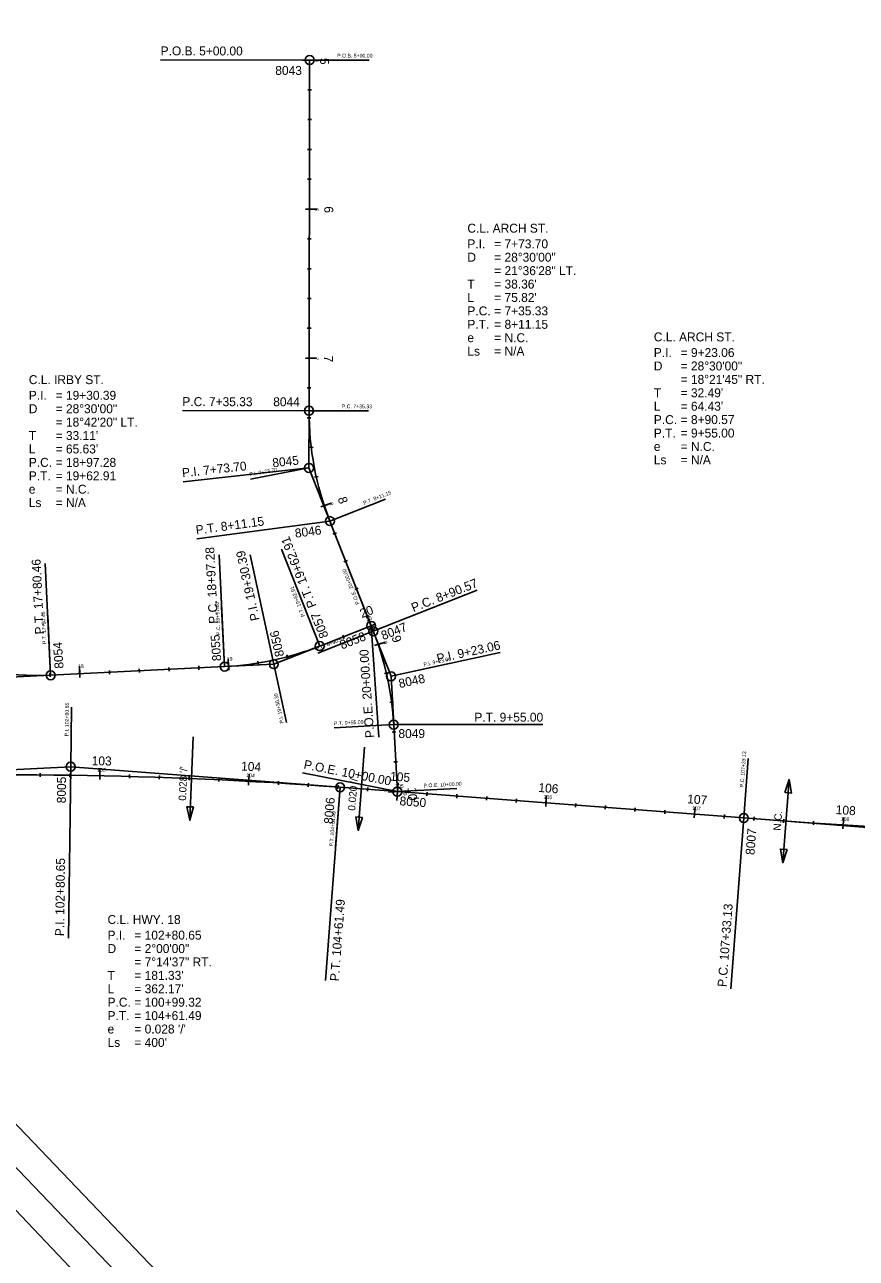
# Model space of a CAD drawing. Extents: x 1708585 to 1714116, y 541444 to 545437.
# Drawn here: x 1712258 to 1712816, y 543987 to 544815 of the extents above; entities that cross this region are included whole.
import ezdxf

# ---------------------------------------------------------------- set-up
doc = ezdxf.new("R2010")
doc.units = 0
for name, color, linetype in [('CL_Highway_1', 7, 'Continuous'), ('CL_Highway_1_40_PText', 7, 'Continuous'), ('CL_Highway_1_40_Sta', 7, 'Continuous'), ('CL_Highway_1_PText', 7, 'Continuous'), ('CL_Highway_1_Sta', 7, 'Continuous'), ('CL_Highway_1_Sta_Minor_Text', 7, 'Continuous'), ('CL_Highway_1_Tangent', 7, 'Continuous'), ('CL_Railroad', 7, 'Continuous'), ('CL_XS_2', 7, 'Continuous'), ('CL_XS_2_40_PText', 7, 'Continuous'), ('CL_XS_2_40_Sta', 7, 'Continuous'), ('CL_XS_2_PText', 7, 'Continuous'), ('CL_XS_2_Sta', 7, 'Continuous'), ('CL_XS_2_Tangent', 7, 'Continuous'), ('CL_XS_3', 7, 'Continuous'), ('CL_XS_3_40_PText', 7, 'Continuous'), ('CL_XS_3_40_Sta', 7, 'Continuous'), ('CL_XS_3_PText', 7, 'Continuous'), ('CL_XS_3_Sta', 7, 'Continuous'), ('CL_XS_3_Sta_Minor_Text', 7, 'Continuous'), ('CL_XS_3_Tangent', 7, 'Continuous'), ('CurveData_100', 7, 'Continuous'), ('Point_CL_Highway_1', 7, 'Continuous'), ('Point_CL_XS_2', 7, 'Continuous'), ('Point_CL_XS_3', 7, 'Continuous'), ('Point_Number', 7, 'Continuous'), ('R_SE_Slope', 7, 'Continuous')]:
    doc.layers.add(name, color=color, linetype=linetype)

msp = doc.modelspace()

# ---------------------------------------------------------------- linework, layer by layer
at = {"layer": 'CL_Highway_1'}
msp.add_line((1712469.8, 544303.56), (1712740.66, 544282.94), dxfattribs=at)
for centre, radius, start, end in [((1712252.32, 541447.04), 2864.79, 85.64618, 92.88967), ((1713175.62, 549995.98), 5729.58, 265.64618, 270.33927)]:
    msp.add_arc(centre, radius, start, end, dxfattribs=at)
at = {"layer": 'CL_Highway_1_40_PText'}
for points in [[(1712288.99, 544317.32), (1712289.51, 544357.32)], [(1712740.66, 544282.94), (1712743.69, 544322.82)], [(1712469.8, 544303.56), (1712466.76, 544263.67)]]:
    msp.add_lwpolyline(points, dxfattribs=at)
at = {"layer": 'CL_Highway_1_40_Sta'}
for points in [[(1712268.52, 544313.03), (1712268.51, 544310.53)], [(1712288.53, 544312.85), (1712288.5, 544310.35)], [(1712308.56, 544313.77), (1712308.46, 544308.77)], [(1712328.54, 544312.06), (1712328.47, 544309.56)], [(1712348.54, 544311.46), (1712348.46, 544308.96)], [(1712368.54, 544310.72), (1712368.43, 544308.22)], [(1712388.52, 544309.84), (1712388.41, 544307.34)], [(1712408.58, 544310.06), (1712408.3, 544305.07)], [(1712428.48, 544307.66), (1712428.33, 544305.16)], [(1712448.45, 544306.36), (1712448.28, 544303.86)], [(1712468.41, 544304.92), (1712468.22, 544302.42)], [(1712488.35, 544303.4), (1712488.16, 544300.91)], [(1712508.39, 544303.13), (1712508.01, 544298.14)], [(1712528.23, 544300.36), (1712528.04, 544297.87)], [(1712548.18, 544298.84), (1712547.99, 544296.35)], [(1712568.12, 544297.33), (1712567.93, 544294.83)], [(1712588.06, 544295.81), (1712587.87, 544293.31)], [(1712608.1, 544295.54), (1712607.72, 544290.55)], [(1712627.94, 544292.77), (1712627.76, 544290.28)], [(1712647.89, 544291.25), (1712647.7, 544288.76)], [(1712667.83, 544289.73), (1712667.64, 544287.24)], [(1712687.77, 544288.22), (1712687.58, 544285.72)], [(1712707.81, 544287.94), (1712707.43, 544282.96)], [(1712727.66, 544285.18), (1712727.47, 544282.69)], [(1712747.6, 544283.66), (1712747.41, 544281.17)], [(1712767.54, 544282.21), (1712767.36, 544279.71)], [(1712787.49, 544280.82), (1712787.32, 544278.32)], [(1712807.52, 544280.74), (1712807.2, 544275.75)]]:
    msp.add_lwpolyline(points, dxfattribs=at)
at = {"layer": 'CL_Highway_1_PText'}
for points in [[(1712288.99, 544317.32), (1712287.53, 544202.33)], [(1712469.8, 544303.56), (1712459.93, 544173.93)], [(1712740.66, 544282.94), (1712731.93, 544168.27)]]:
    msp.add_lwpolyline(points, dxfattribs=at)
at = {"layer": 'CL_Highway_1_Sta'}
for points in [[(1712308.61, 544316.27), (1712308.51, 544311.27)], [(1712408.71, 544312.56), (1712408.44, 544307.57)], [(1712508.65, 544306.62), (1712507.74, 544294.65)], [(1712608.29, 544298.03), (1712607.91, 544293.04)], [(1712708, 544290.44), (1712707.62, 544285.45)], [(1712807.68, 544283.24), (1712807.36, 544278.25)]]:
    msp.add_lwpolyline(points, dxfattribs=at)
at = {"layer": 'CL_Highway_1_Tangent'}
for p, q in [((1712107.9, 544308.18), (1712288.99, 544317.32)), ((1712288.99, 544317.32), (1712469.8, 544303.56)), ((1712740.66, 544282.94), (1712974.76, 544265.11))]:
    msp.add_line(p, q, dxfattribs=at)
at = {"layer": 'CL_Railroad'}
for p, q in [((1710952.7, 545436.87), (1713371.13, 542906.81)), ((1710938.24, 545423.05), (1713356.67, 542892.99)), ((1710923.78, 545409.23), (1713342.21, 542879.17))]:
    msp.add_line(p, q, dxfattribs=at)
at = {"layer": 'CL_XS_2'}
for p, q in [((1712456.08, 544398.29), (1712490.59, 544411.89)), ((1712275.53, 544378.82), (1712392.21, 544384.53))]:
    msp.add_line(p, q, dxfattribs=at)
for centre, start, end in [((1712265.7, 544579.61), 224.05036, 272.80306), ((1712382.38, 544585.33), 272.80306, 291.50855)]:
    msp.add_arc(centre, 201.04, start, end, dxfattribs=at)
at = {"layer": 'CL_XS_2_40_PText'}
for points in [[(1712490.59, 544411.89), (1712475.93, 544449.1)], [(1712456.08, 544398.29), (1712441.42, 544435.5)], [(1712392.21, 544384.53), (1712390.25, 544424.48)], [(1712275.53, 544378.82), (1712273.57, 544418.77)], [(1712425.28, 544386.15), (1712433.7, 544347.05)]]:
    msp.add_lwpolyline(points, dxfattribs=at)
at = {"layer": 'CL_XS_2_40_Sta'}
for points in [[(1712489.68, 544414.21), (1712491.51, 544409.56)], [(1712471.53, 544405.72), (1712472.44, 544403.39)], [(1712452.93, 544398.41), (1712453.81, 544396.07)], [(1712434.02, 544392.33), (1712434.66, 544389.91)], [(1712294.93, 544382.27), (1712295.17, 544377.28)], [(1712314.96, 544382), (1712315.08, 544379.5)], [(1712334.94, 544382.98), (1712335.06, 544380.48)], [(1712354.91, 544383.96), (1712355.04, 544381.46)], [(1712374.89, 544384.93), (1712375.01, 544382.44)], [(1712394.77, 544387.18), (1712395.08, 544382.19)], [(1712414.59, 544388.15), (1712414.99, 544385.69)], [(1712275.01, 544380.04), (1712275.13, 544377.55)]]:
    msp.add_lwpolyline(points, dxfattribs=at)
at = {"layer": 'CL_XS_2_PText'}
for points in [[(1712456.08, 544398.29), (1712430.42, 544463.42)], [(1712388.54, 544459.44), (1712392.21, 544384.53)], [(1712409.49, 544459.47), (1712425.28, 544386.15)], [(1712271.86, 544453.73), (1712275.53, 544378.82)], [(1712490.59, 544411.89), (1712495.76, 544337.07)]]:
    msp.add_lwpolyline(points, dxfattribs=at)
at = {"layer": 'CL_XS_2_Sta'}
for p, q in [((1712492.43, 544407.24), (1712488.76, 544416.54)), ((1712394.93, 544384.68), (1712394.61, 544389.67)), ((1712295.05, 544379.77), (1712294.8, 544384.77))]:
    msp.add_line(p, q, dxfattribs=at)
at = {"layer": 'CL_XS_2_Tangent'}
for points in [[(1712121.21, 544439.84), (1712184.54, 544374.36), (1712275.53, 544378.82)], [(1712392.21, 544384.53), (1712425.28, 544386.15), (1712456.08, 544398.29)]]:
    msp.add_lwpolyline(points, dxfattribs=at)
at = {"layer": 'CL_XS_3'}
for p, q in [((1712449.32, 544791.52), (1712448.91, 544556.19)), ((1712462.91, 544482.13), (1712492.03, 544408.24)), ((1712505.73, 544345.57), (1712508.2, 544300.63))]:
    msp.add_line(p, q, dxfattribs=at)
for centre, start, end in [((1712649.95, 544555.84), 179.90067, 201.50855), ((1712304.99, 544334.53), 3.14618, 21.50855)]:
    msp.add_arc(centre, 201.04, start, end, dxfattribs=at)
at = {"layer": 'CL_XS_3_40_PText'}
for points in [[(1712449.32, 544791.52), (1712489.32, 544791.45)], [(1712448.91, 544556.19), (1712488.91, 544556.12)], [(1712448.85, 544517.82), (1712409.54, 544510.39)], [(1712462.91, 544482.13), (1712500.13, 544496.8)], [(1712492.03, 544408.24), (1712454.82, 544393.58)], [(1712503.94, 544378.01), (1712543.02, 544386.55)], [(1712505.73, 544345.57), (1712465.79, 544343.37)], [(1712508.2, 544300.63), (1712548.14, 544302.83)]]:
    msp.add_lwpolyline(points, dxfattribs=at)
at = {"layer": 'CL_XS_3_40_Sta'}
for points in [[(1712451.82, 544791.52), (1712446.82, 544791.52)], [(1712450.54, 544771.52), (1712448.04, 544771.52)], [(1712450.5, 544751.52), (1712448, 544751.52)], [(1712450.47, 544731.52), (1712447.97, 544731.52)], [(1712450.43, 544711.52), (1712447.93, 544711.52)], [(1712451.65, 544691.52), (1712446.65, 544691.53)], [(1712450.36, 544671.52), (1712447.86, 544671.52)], [(1712450.33, 544651.52), (1712447.83, 544651.52)], [(1712450.29, 544631.52), (1712447.79, 544631.52)], [(1712450.26, 544611.52), (1712447.76, 544611.52)], [(1712451.47, 544591.52), (1712446.47, 544591.53)], [(1712450.19, 544571.52), (1712447.69, 544571.52)], [(1712450.21, 544551.55), (1712447.71, 544551.49)], [(1712451.62, 544531.73), (1712449.14, 544531.43)], [(1712455, 544512.15), (1712452.56, 544511.61)], [(1712461.49, 544493.4), (1712456.74, 544491.83)], [(1712467.32, 544474.36), (1712464.99, 544473.44)], [(1712474.65, 544455.75), (1712472.33, 544454.83)], [(1712481.98, 544437.14), (1712479.66, 544436.22)], [(1712489.32, 544418.53), (1712486.99, 544417.62)], [(1712497.65, 544400.2), (1712492.91, 544398.58)], [(1712502, 544380.45), (1712499.56, 544379.89)], [(1712505.58, 544360.66), (1712503.11, 544360.34)], [(1712507.25, 544340.64), (1712504.75, 544340.51)], [(1712508.35, 544320.67), (1712505.85, 544320.54)], [(1712510.69, 544300.77), (1712505.7, 544300.5)]]:
    msp.add_lwpolyline(points, dxfattribs=at)
at = {"layer": 'CL_XS_3_PText'}
for points in [[(1712449.32, 544791.52), (1712349.32, 544791.69)], [(1712448.91, 544556.19), (1712363.91, 544556.33)], [(1712448.85, 544517.82), (1712364.35, 544508.59)], [(1712462.91, 544482.13), (1712373.71, 544470.18)], [(1712492.03, 544408.24), (1712561.81, 544435.74)], [(1712503.94, 544378.01), (1712577.21, 544394.02)], [(1712505.73, 544345.57), (1712605.73, 544345.56)], [(1712508.2, 544300.63), (1712444.42, 544313.18)]]:
    msp.add_lwpolyline(points, dxfattribs=at)
at = {"layer": 'CL_XS_3_Sta'}
for p, q in [((1712454.32, 544791.51), (1712444.32, 544791.53)), ((1712454.15, 544691.51), (1712449.15, 544691.52)), ((1712453.97, 544591.51), (1712448.97, 544591.52)), ((1712463.86, 544494.19), (1712459.11, 544492.61)), ((1712500.01, 544401), (1712495.28, 544399.39)), ((1712514.19, 544300.96), (1712502.21, 544300.3))]:
    msp.add_line(p, q, dxfattribs=at)
at = {"layer": 'CL_XS_3_Tangent'}
for points in [[(1712448.91, 544556.19), (1712448.85, 544517.82), (1712462.91, 544482.13)], [(1712492.03, 544408.24), (1712503.94, 544378.01), (1712505.73, 544345.57)]]:
    msp.add_lwpolyline(points, dxfattribs=at)
at = {"layer": 'Point_CL_Highway_1'}
for centre in [(1712288.99, 544317.32), (1712469.8, 544303.56), (1712740.66, 544282.94)]:
    msp.add_circle(centre, 3, dxfattribs=at)
at = {"layer": 'Point_CL_XS_2'}
for centre in [(1712490.59, 544411.89), (1712456.08, 544398.29), (1712425.28, 544386.15), (1712275.53, 544378.74), (1712392.21, 544384.53)]:
    msp.add_circle(centre, 3, dxfattribs=at)
at = {"layer": 'Point_CL_XS_3'}
msp.add_lwpolyline([(1712490.59, 544411.89), (1712489.49, 544414.68), (1712490.59, 544411.89), (1712487.8, 544410.79), (1712490.59, 544411.89), (1712491.69, 544409.1), (1712490.59, 544411.89), (1712493.38, 544412.99)], dxfattribs=at)
for centre in [(1712449.32, 544791.52), (1712448.91, 544556.19), (1712448.85, 544517.82), (1712462.91, 544482.13), (1712492.03, 544408.24), (1712503.94, 544378.01), (1712505.73, 544345.57), (1712508.2, 544300.63)]:
    msp.add_circle(centre, 3, dxfattribs=at)
at = {"layer": 'R_SE_Slope'}
for p, q in [((1712368.83, 544281.43), (1712371.13, 544337.38)), ((1712481.92, 544274.55), (1712486.17, 544330.39)), ((1712766.81, 544252.93), (1712771.07, 544308.77))]:
    msp.add_line(p, q, dxfattribs=at)
for points in [[(1712768.14, 544299.97), (1712772.63, 544299.63), (1712771.07, 544308.77)], [(1712371.44, 544290.33), (1712366.95, 544290.52), (1712368.83, 544281.43)], [(1712484.85, 544283.36), (1712480.36, 544283.7), (1712481.92, 544274.55)], [(1712769.74, 544261.74), (1712765.25, 544262.08), (1712766.81, 544252.93)]]:
    msp.add_lwpolyline(points, close=True, dxfattribs=at)

# ---------------------------------------------------------------- texts
at = {"layer": 'CL_Highway_1_40_PText'}
for s, rotation, p in [('P.I. 102+80.65', 89.26792, (1712287.51, 544337.75)), ('P.C. 107+33.13', 85.64618, (1712740.47, 544303.58)), ('P.T. 104+61.49', 85.64618, (1712465.02, 544263.81))]:
    msp.add_text(s, height=2.5, rotation=rotation, dxfattribs=at).set_placement(p)
at = {"layer": 'CL_Highway_1_40_Sta'}
for s, rotation, p in [('103', 358.87604, (1712306.69, 544314.06)), ('104', 356.87604, (1712406.72, 544310.42)), ('105', 355.64618, (1712506.54, 544303.52)), ('106', 355.64618, (1712606.19, 544295.93)), ('107', 355.64618, (1712705.96, 544288.34)), ('108', 356.31486, (1712805.67, 544281.11))]:
    msp.add_text(s, height=2.5, rotation=rotation, dxfattribs=at).set_placement(p)
at = {"layer": 'CL_Highway_1_PText'}
for s, rotation, p in [('P.I. 102+80.65', 89.26792, (1712284.54, 544203.62)), ('P.T. 104+61.49', 85.64618, (1712468.91, 544173.25)), ('P.C. 107+33.13', 85.64618, (1712729, 544169.39))]:
    msp.add_text(s, height=6, rotation=rotation, dxfattribs=at).set_placement(p)
at = {"layer": 'CL_Highway_1_Sta'}
msp.add_text('105', height=6, rotation=355.64618, dxfattribs=at).set_placement((1712503.12, 544308.04))
at = {"layer": 'CL_Highway_1_Sta_Minor_Text'}
for s, rotation, p in [('103', 358.87604, (1712303.03, 544318.38)), ('104', 356.87604, (1712403.21, 544314.86)), ('106', 355.64618, (1712602.67, 544300.46)), ('107', 355.64618, (1712702.54, 544292.86)), ('108', 356.31486, (1712802.2, 544285.6))]:
    msp.add_text(s, height=6, rotation=rotation, dxfattribs=at).set_placement(p)
at = {"layer": 'CL_XS_2_40_PText'}
for s, rotation, p in [('P.O.E. 20+00.00', 111.50855, (1712482.87, 544426.7)), ('P.T. 19+62.91', 111.50855, (1712446.26, 544418.45)), ('P.C. 18+97.28', 92.80306, (1712389.41, 544405.81)), ('P.T. 17+80.46', 92.80306, (1712272.75, 544399.76)), ('P.I. 19+30.39', 102.15581, (1712431.99, 544346.68))]:
    msp.add_text(s, height=2.5, rotation=rotation, dxfattribs=at).set_placement(p)
at = {"layer": 'CL_XS_2_40_Sta'}
for s, rotation, p in [('20', 21.50855, (1712487.77, 544414.81)), ('19', 3.57942, (1712393.79, 544388.37)), ('18', 2.80306, (1712293.97, 544383.48))]:
    msp.add_text(s, height=2.5, rotation=rotation, dxfattribs=at).set_placement(p)
at = {"layer": 'CL_XS_2_PText'}
for s, rotation, p in [('P.T. 19+62.91', 111.50855, (1712454.03, 544425.32)), ('P.C. 18+97.28', 92.80306, (1712387.79, 544413.41)), ('P.T. 17+80.46', 92.80306, (1712271.18, 544406.28)), ('P.I. 19+30.39', 102.15581, (1712415.8, 544415.92)), ('P.O.E. 20+00.00', 93.94778, (1712492.76, 544336.86))]:
    msp.add_text(s, height=6, rotation=rotation, dxfattribs=at).set_placement(p)
at = {"layer": 'CL_XS_2_Sta'}
msp.add_text('20', height=6, rotation=21.50855, dxfattribs=at).set_placement((1712484.42, 544416.98))
at = {"layer": 'CL_XS_3_40_PText'}
for s, rotation, p in [('P.O.B. 5+00.00', 359.90067, (1712467.8, 544793.24)), ('P.C. 7+35.33', 359.90067, (1712470.96, 544557.9)), ('P.I. 7+73.70', 10.70461, (1712409.22, 544512.11)), ('P.T. 8+11.15', 21.50855, (1712485.89, 544493.07)), ('P.C. 8+90.57', 21.50855, (1712454.17, 544395.2)), ('P.I. 9+23.06', 12.32737, (1712526.05, 544384.63)), ('P.T. 9+55.00', 3.14618, (1712465.69, 544345.12)), ('P.O.E. 10+00.00', 3.14618, (1712525.82, 544303.36))]:
    msp.add_text(s, height=2.5, rotation=rotation, dxfattribs=at).set_placement(p)
at = {"layer": 'CL_XS_3_40_Sta'}
for s, rotation, p in [('5', 269.90067, (1712453.07, 544792.08)), ('6', 269.90067, (1712452.9, 544692.14)), ('7', 269.90067, (1712452.72, 544592.08)), ('8', 288.33048, (1712462.49, 544494.33)), ('9', 288.82118, (1712498.64, 544401.14)), ('10', 273.14618, (1712511.89, 544301.82))]:
    msp.add_text(s, height=2.5, rotation=rotation, dxfattribs=at).set_placement(p)
at = {"layer": 'CL_XS_3_PText'}
for s, rotation, p in [('P.O.B. 5+00.00', 359.90067, (1712349.33, 544794.69)), ('P.C. 7+35.33', 359.90067, (1712363.92, 544559.33)), ('P.I. 7+73.70', 6.23429, (1712364.02, 544511.57)), ('P.T. 8+11.15', 7.63179, (1712373.31, 544473.15)), ('P.C. 8+90.57', 21.50855, (1712518.95, 544421)), ('P.I. 9+23.06', 12.32737, (1712535.29, 544386.91)), ('P.T. 9+55.00', 359.99717, (1712559.86, 544347.56)), ('P.O.E. 10+00.00', 348.86707, (1712445, 544316.13))]:
    msp.add_text(s, height=6, rotation=rotation, dxfattribs=at).set_placement(p)
at = {"layer": 'CL_XS_3_Sta'}
for s, rotation, p in [('5', 269.90067, (1712456.32, 544792.93)), ('10', 273.14618, (1712515.05, 544303.48))]:
    msp.add_text(s, height=6, rotation=rotation, dxfattribs=at).set_placement(p)
at = {"layer": 'CL_XS_3_Sta_Minor_Text'}
for s, rotation, p in [('6', 269.90067, (1712459.15, 544693.37)), ('7', 269.90067, (1712458.98, 544593.2)), ('8', 288.33048, (1712468.07, 544497.37)), ('9', 288.82118, (1712504.19, 544404.25))]:
    msp.add_text(s, height=6, rotation=rotation, dxfattribs=at).set_placement(p)
at = {"layer": 'CurveData_100'}
for s, p in [('C.L. ARCH ST.', (1712555.17, 544675.7)), ('P.I.', (1712555.17, 544665.2)), ('= 7+73.70', (1712573.17, 544665.2)), ('D', (1712555.17, 544656.2)), ('= 28%%d30\'00"', (1712573.17, 544656.2)), ('= 21%%d36\'28" LT.', (1712573.17, 544647.2)), ('T', (1712555.17, 544638.2)), ("= 38.36'", (1712573.17, 544638.2)), ('L', (1712555.17, 544629.2)), ("= 75.82'", (1712573.17, 544629.2)), ('P.C.', (1712555.17, 544620.2)), ('= 7+35.33', (1712573.17, 544620.2)), ('P.T.', (1712555.17, 544611.2)), ('= 8+11.15', (1712573.17, 544611.2)), ('e', (1712555.17, 544602.2)), ('= N.C.', (1712573.17, 544602.2)), ('C.L. ARCH ST.', (1712680.27, 544602.74)), ('Ls', (1712555.17, 544593.2)), ('= N/A', (1712573.17, 544593.2)), ('P.I.', (1712680.27, 544592.24)), ('= 9+23.06', (1712698.27, 544592.24)), ('D', (1712680.27, 544583.24)), ('= 28%%d30\'00"', (1712698.27, 544583.24)), ('C.L. IRBY ST.', (1712260.88, 544574.06)), ('= 18%%d21\'45" RT.', (1712698.27, 544574.24)), ('T', (1712680.27, 544565.24)), ("= 32.49'", (1712698.27, 544565.24)), ('P.I.', (1712260.88, 544563.56)), ('= 19+30.39', (1712278.88, 544563.56)), ('D', (1712260.88, 544554.56)), ('= 28%%d30\'00"', (1712278.88, 544554.56)), ('L', (1712680.27, 544556.24)), ("= 64.43'", (1712698.27, 544556.24)), ('= 18%%d42\'20" LT.', (1712278.88, 544545.56)), ('P.C.', (1712680.27, 544547.24)), ('= 8+90.57', (1712698.27, 544547.24)), ('T', (1712260.88, 544536.56)), ("= 33.11'", (1712278.88, 544536.56)), ('P.T.', (1712680.27, 544538.24)), ('= 9+55.00', (1712698.27, 544538.24)), ('L', (1712260.88, 544527.56)), ("= 65.63'", (1712278.88, 544527.56)), ('e', (1712680.27, 544529.24)), ('= N.C.', (1712698.27, 544529.24)), ('P.C.', (1712260.88, 544518.56)), ('= 18+97.28', (1712278.88, 544518.56)), ('Ls', (1712680.27, 544520.24)), ('= N/A', (1712698.27, 544520.24)), ('P.T.', (1712260.88, 544509.56)), ('= 19+62.91', (1712278.88, 544509.56)), ('e', (1712260.88, 544500.56)), ('= N.C.', (1712278.88, 544500.56)), ('Ls', (1712260.88, 544491.56)), ('= N/A', (1712278.88, 544491.56)), ('C.L. HWY. 18', (1712313.71, 544211.83)), ('P.I.', (1712313.71, 544201.33)), ('= 102+80.65', (1712331.71, 544201.33)), ('= 2%%d00\'00"', (1712331.71, 544192.33)), ('D', (1712313.71, 544192.33)), ('= 7%%d14\'37" RT.', (1712331.71, 544183.33)), ('T', (1712313.71, 544174.33)), ("= 181.33'", (1712331.71, 544174.33)), ('L', (1712313.71, 544165.33)), ("= 362.17'", (1712331.71, 544165.33)), ('P.C.', (1712313.71, 544156.33)), ('= 100+99.32', (1712331.71, 544156.33)), ('P.T.', (1712313.71, 544147.33)), ('= 104+61.49', (1712331.71, 544147.33)), ('e', (1712313.71, 544138.33)), ("= 0.028 '/'", (1712331.71, 544138.33)), ('Ls', (1712313.71, 544129.33)), ("= 400'", (1712331.71, 544129.33))]:
    msp.add_text(s, height=6, dxfattribs=at).set_placement(p)
at = {"layer": 'Point_Number'}
for s, rotation, p in [('8043', 359.90067, (1712426.27, 544781.56)), ('8044', 359.90067, (1712424.89, 544559.23)), ('8045', 6.23429, (1712424.63, 544518.2)), ('8046', 7.63179, (1712439.83, 544470.97)), ('8057', 111.50855, (1712462.06, 544404.94)), ('8047', 21.50855, (1712498.7, 544402.22)), ('8055', 93.93621, (1712390.02, 544388.39)), ('8056', 102.72238, (1712432.24, 544391.82)), ('8058', 21.50855, (1712471.04, 544395.97)), ('8054', 93.93621, (1712284.24, 544383.37)), ('8048', 12.32737, (1712509.77, 544370.07)), ('8049', 359.99717, (1712508.89, 544336.57)), ('8005', 89.26792, (1712285.68, 544292.77)), ('8006', 85.64618, (1712464.9, 544278.74)), ('8050', 355.64618, (1712509.49, 544291.51)), ('8007', 85.64618, (1712747.78, 544257.95))]:
    msp.add_text(s, height=6, rotation=rotation, dxfattribs=at).set_placement(p)
at = {"layer": 'R_SE_Slope'}
for s, rotation, p in [("0.028 '/'", 87.64617, (1712366.36, 544294.45)), ("0.020 '/'", 85.64618, (1712479.91, 544287.69)), ('N.C.', 85.64618, (1712765.43, 544274.29))]:
    msp.add_text(s, height=5, rotation=rotation, dxfattribs=at).set_placement(p)

doc.saveas('drawing.dxf')
